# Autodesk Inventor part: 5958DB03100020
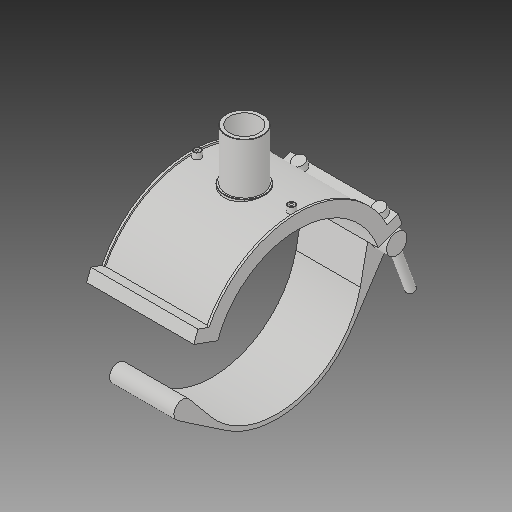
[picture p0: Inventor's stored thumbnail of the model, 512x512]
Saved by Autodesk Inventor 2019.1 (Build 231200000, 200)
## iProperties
Created: 2017-07
Part Number: 5958DB03100020
Material: Generic
Description: PLASSON BRANCH SADDLE 10''DIPS x 2''IPS
Document SubType Name: Modeling
Designer: KIM
Mass: 764.267 g
Surface Area: 1930.38 cm^2
Volume: 764.267 cm^3
Density: 1 g/cm^3
Appearance: Default
Author: KIM
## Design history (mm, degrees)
derived "5958D (2).ipt"
feature "Solid6::5958D (2).ipt"
tag "TaggingFeature1"
body "Solid1"
other parameters: "d_" = 280.6, "d1" = 60.1, "B_" = 180.594, "H_" = 104.902, "H1" = 84.074, "L" = 176.022, "t" = 6, "d244" = 280.6, "d245" = 20.828, "d248" = 180.594, "d249" = 90.297, "d252" = 140.3, "d254" = 20.828, "d256" = 541.782, "d257" = 35.075, "d258" = 270.891, "d259" = 0.5, "d260" = 176.022, "d261" = 0, "d287" = 161.96112, "d288" = 66.11, "d290" = 0, "d291" = 245.202, "d292" = 60.1, "d294" = 0, "d309" = 170.3, "d310" = 12, "d311" = 12, "d315" = 3 deg, "d316" = 4, "d318" = 4, "d320" = 14, "d321" = 0, "d331" = 0.601, "d332" = 48.08, "d334" = 0, "d337" = 0.601, "d340" = 10.56132, "d341" = 10.56132, "d342" = 20 deg, "d343" = 20 deg, "d344" = 722.376, "d345" = 280.6, "d347" = 0, "d352" = 41.656, "d353" = 19.642, "d355" = 0, "d356" = 20 deg, "d357" = 42.09, "d358" = 280.6, "d359" = 294.63, "d360" = 33.672, "d361" = 10 deg, "d362" = 9.26846, "d363" = 56.12, "d366" = 154.33, "d367" = 9.68502, "d368" = 105.6132, "d369" = 0, "d370" = 158.4198, "d371" = 0, "d372" = 132.0165, "d374" = 14.03, "d375" = 19.642, "d376" = 14.03, "d377" = 19.642, "d378" = 140.3, "d379" = 0, "d380" = 11.7852, "d381" = 0, "d383" = 171.542, "d384" = 17.6022, "d385" = 2.806, "d386" = 3.52044, "d387" = 0, "d389" = 360 deg
